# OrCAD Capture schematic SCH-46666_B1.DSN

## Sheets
1 P02_TABLES AND NOTES: title: PCF85063AT-ARD; rev: B1; company: NXP Semiconductors; note: SCH-46666 PDF: SPF-46666; note: 6501 William Cannon Drive West; note: Austin, TX 78735-8598
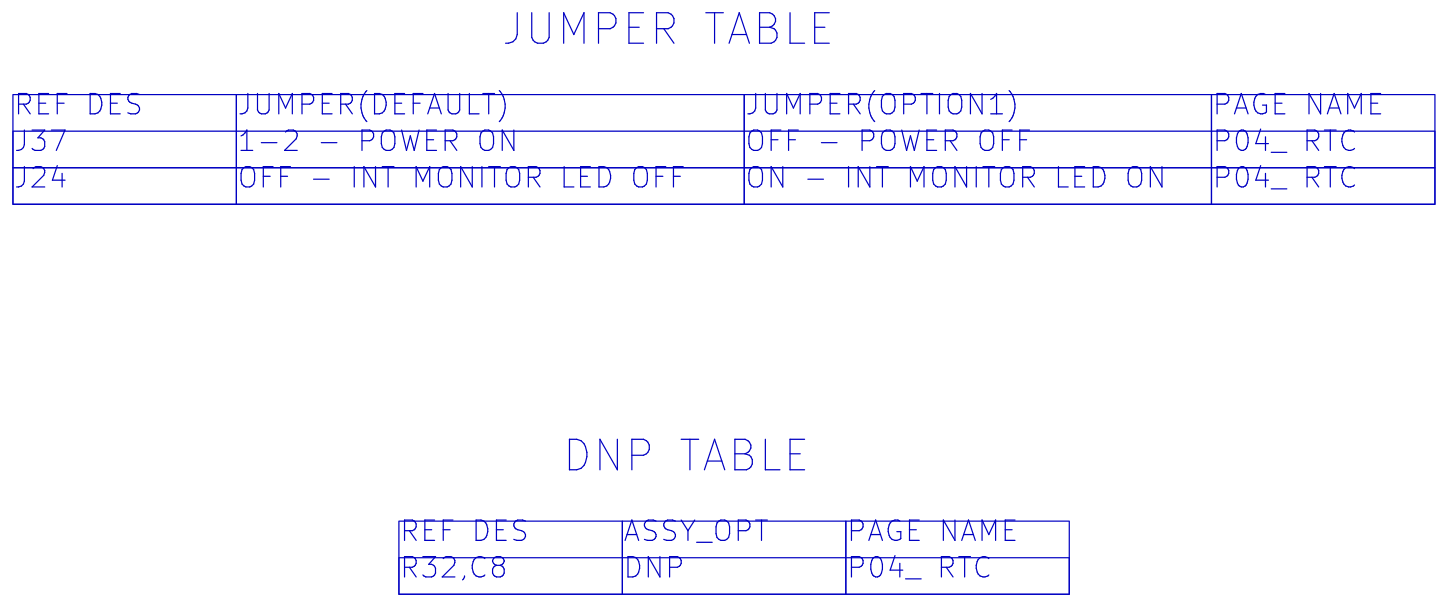
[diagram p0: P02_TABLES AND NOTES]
2 P01_COVER_PAGE
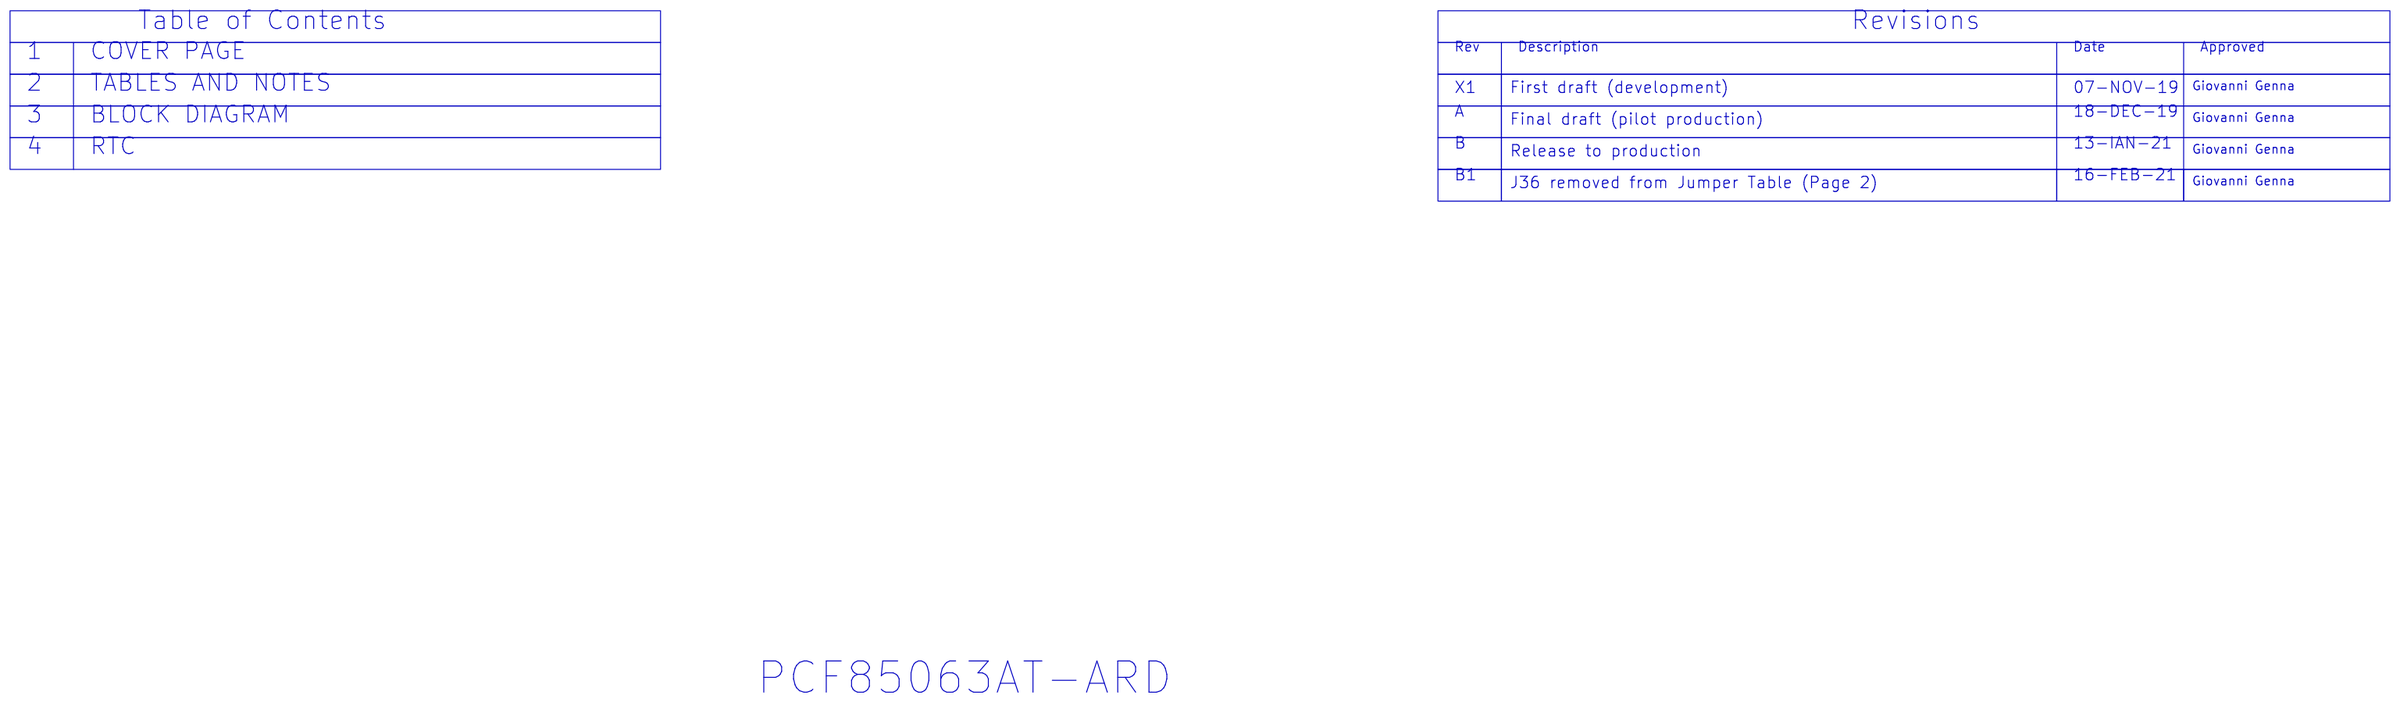
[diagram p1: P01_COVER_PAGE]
3 P03_BLOCK_DIAGRAM
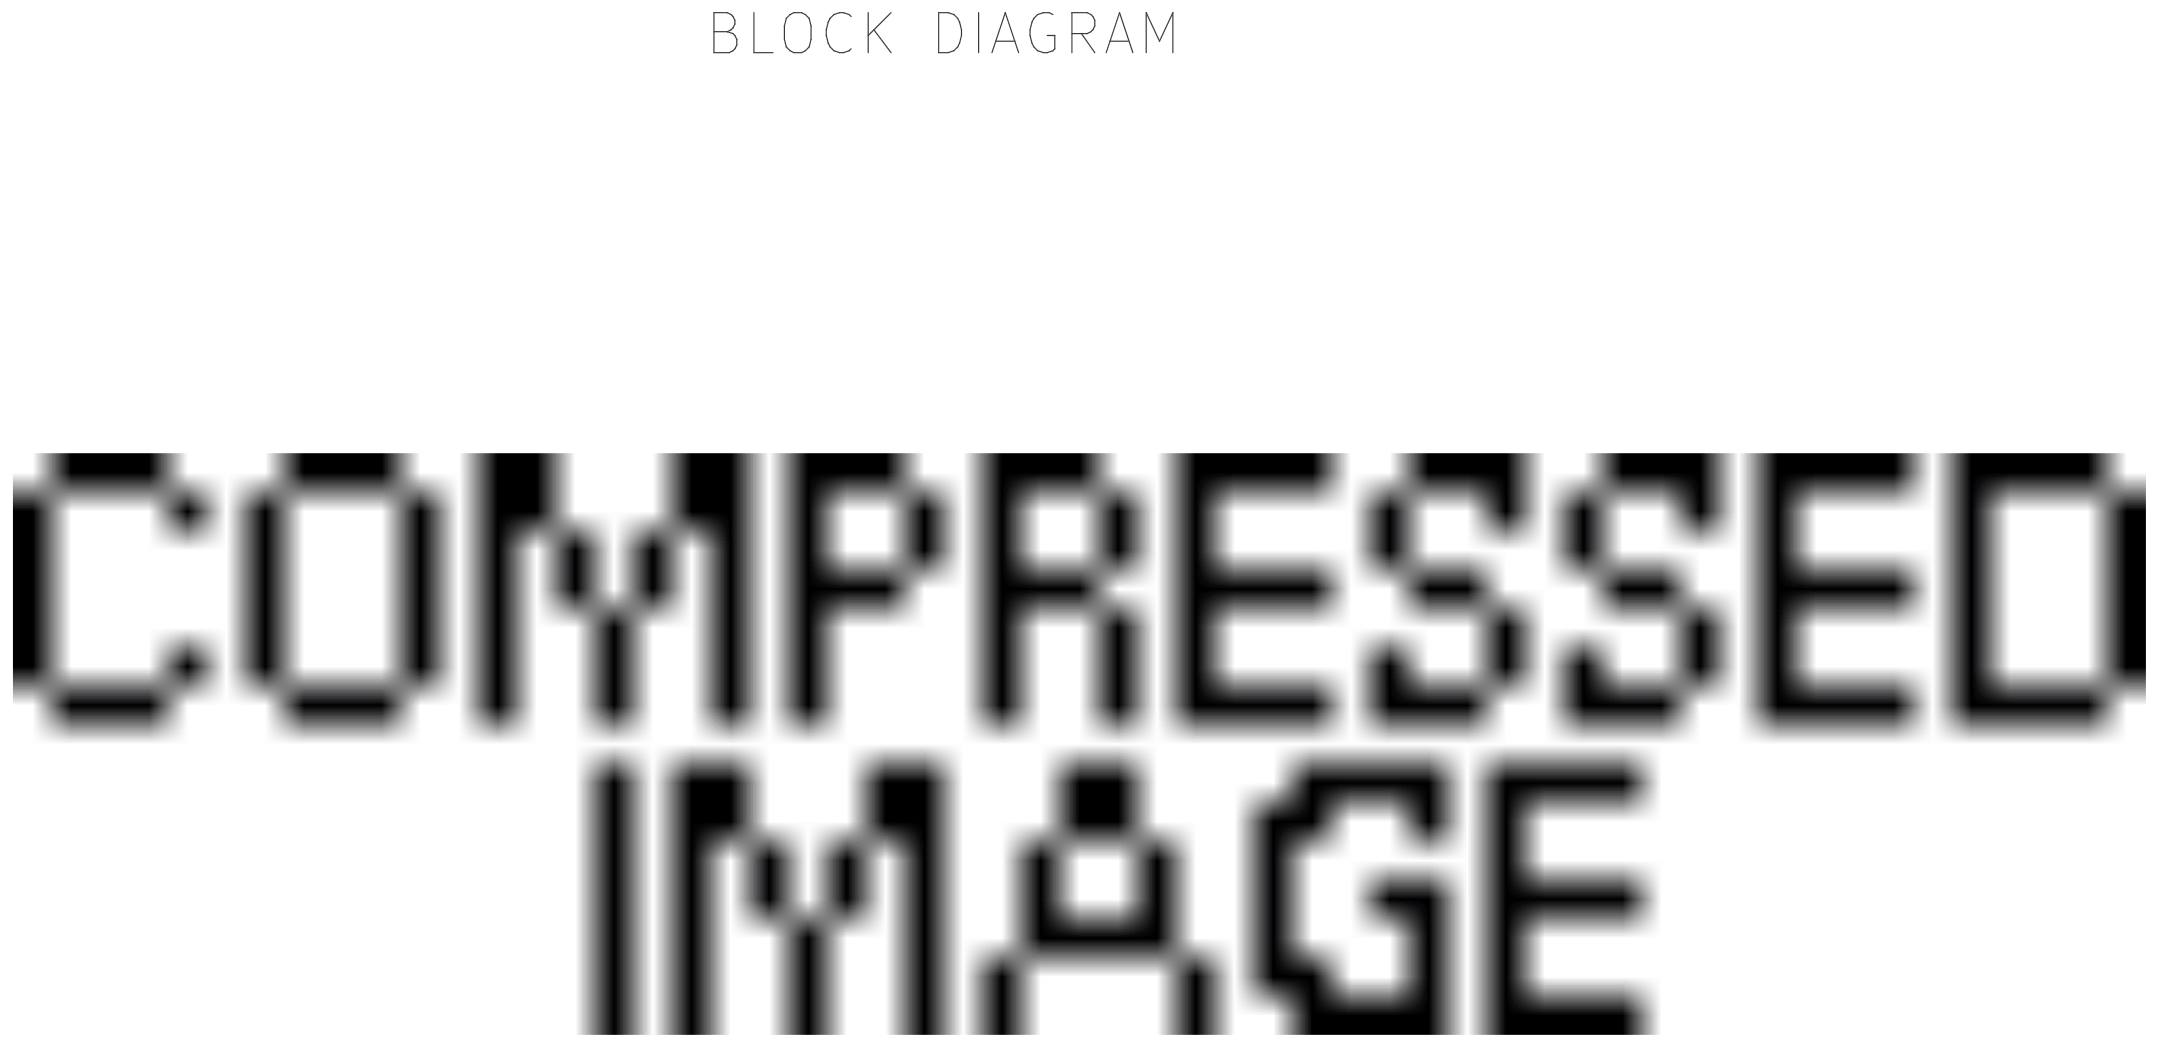
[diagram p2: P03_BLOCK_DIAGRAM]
4 P04_ RTC: size C
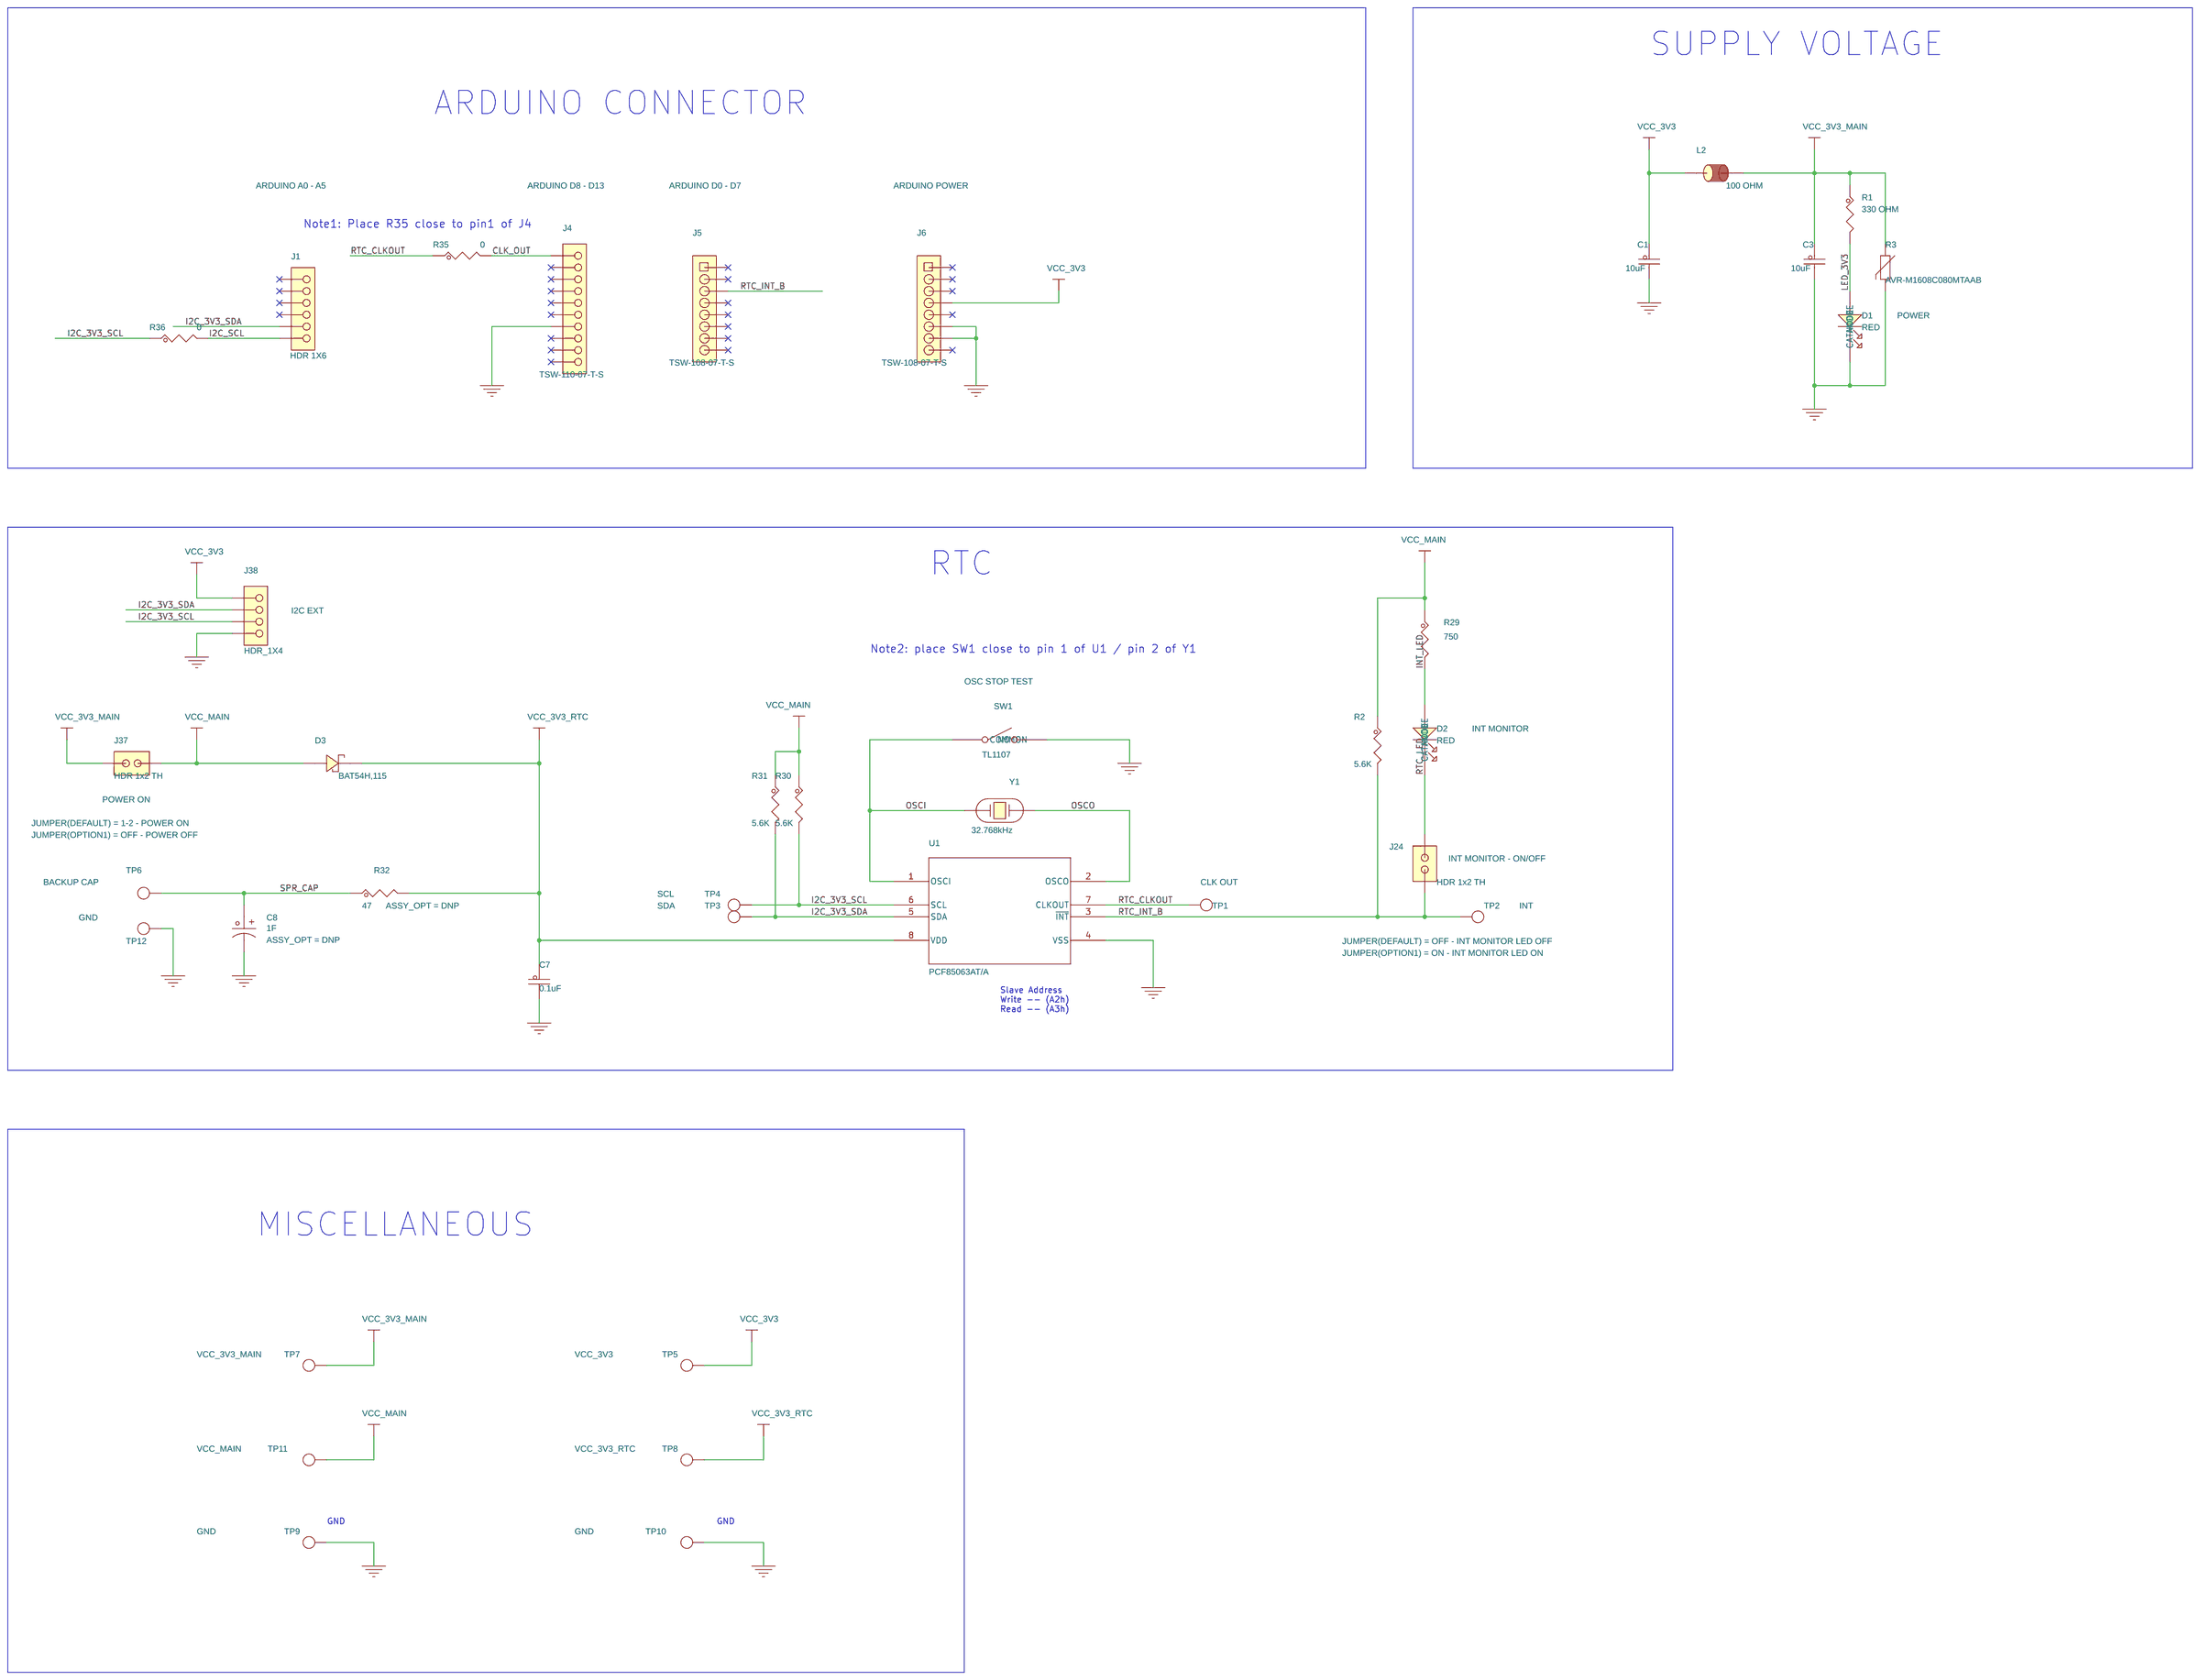
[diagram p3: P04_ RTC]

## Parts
C1  10uF  [CC0603_OV]
C3  10uF  [CC0603_OV]
C7  0.1uF  [CC0402_25]
C8  1F  [cap_5x19p2_th]
D1  RED  [led_2p_0805]
D2  RED  [led_2p_0805]
D3  BAT54H,115  [sod123w]
J1  HDR 1X6  [hdr106_th_tsw]
J4  TSW-110-07-T-S  [hdr110]
J5  TSW-108-07-T-S  [JUMP1X8-6040]
J6  TSW-108-07-T-S  [JUMP1X8-6040]
J24  HDR 1x2 TH  [hdr102_78mil_th]
J37  HDR 1x2 TH  [hdr102_78mil_th]
J38  HDR_1X4  [hdr104_2p54_th]
L2  100 OHM  [IND_1206A]
R1  330 OHM  [RC0402_25]
R2  5.6K  [RC0402_25]
R3  AVR-M1608C080MTAAB  [RC0603_OV]
R29  750  [RC0402_25]
R30  5.6K  [RC0402_25]
R31  5.6K  [RC0402_25]
R32  47  [RC0402_25]
R35  0  [RC0402_25]
R36  0  [RC0402_25]
SW1  TL1107  [sw2_6p5_6x3mm_th]
TP1  TPAD_028  [TPAD_028]
TP2  TPAD_028  [TPAD_028]
TP3  TPAD_028  [TPAD_028]
TP4  TPAD_028  [TPAD_028]
TP5  TPAD_028  [TPAD_028]
TP6  TPAD_028  [TPAD_028]
TP7  TPAD_028  [TPAD_028]
TP8  TPAD_028  [TPAD_028]
TP9  TPAD_028  [TPAD_028]
TP10  TPAD_028  [TPAD_028]
TP11  TPAD_028  [TPAD_028]
TP12  TPAD_028  [TPAD_028]
U1  PCF85063AT/A  [so8_1p27_4x5]
Y1  32.768kHz  [XTAL2-3p2x1p5-SM]

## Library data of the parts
C1 C3 = CAP_NP: CAP CER 10uF 25V 20% X5R 0603; AGILE_PN: 150-79272; CAD_APPROVED: Yes; FPLIST: CC0603_OV,CC0603; HEIGHT: 1MM; MFG_NAME01: MURATA; MFG_PN01: GRM188R61E106MA73D; Package Size: 0603; ROHS: Yes; Tolerance: 20%; VOLTAGE: 25V
C7 = CAP_NP: CAP CER 0.1uF 50V 10% X7R 0402; AGILE_PN: 150-79069; CAD_APPROVED: Yes; FPLIST: CC0402_25,CC0402_HD,0402_CC; HEIGHT: 0.6 MM; MFG_NAME01: MURATA; MFG_PN01: GRM155R71H104KE14D; ROHS: Yes; Tolerance: 10%; VOLTAGE: 50V
C8 = CAP_POL: CAP ACTVTD CRBN 1F 5.5V +80/-20% -- RADIAL; AGILE_PN: 150-80363; ASSY_OPT: DNP; CAD_APPROVED: Yes; HEIGHT: 19.5MM; MFG_NAME01: EATON; MFG_PN01: KR-5R5V105-R; ROHS: Yes; Temp Range: -25C to +70C; Temp_Range: -25C to +70C
D1 = LED: LED RED CLEAR SGL 30MA 0805; AGILE_PN: 370-76455; CAD_APPROVED: Yes; FPLIST: led_2p_0805,led0805; HEIGHT: 1.2MM; MFG_NAME01: LITE ON; MFG_PN01: LTST-C170EKT; ROHS: Yes; SILK: POWER; VOLTAGE: 5V
D2 = LED: LED RED CLEAR SGL 30MA 0805; AGILE_PN: 370-76455; CAD_APPROVED: Yes; FPLIST: led_2p_0805,led0805; HEIGHT: 1.2MM; MFG_NAME01: LITE ON; MFG_PN01: LTST-C170EKT; ROHS: Yes; SILK: INT MONITOR; VOLTAGE: 5V
D3 = DIODE_SCHTKY: DIODE SCH 200MA 30V AEC-Q101 SOD123F; AGILE_PN: 480-79798; CAD_APPROVED: Yes; HEIGHT: 1.2MM; MFG_NAME01: NEXPERIA; ROHS: Yes; Temp Range: -65 to + 125°C; Temp_Range: -65 to + 125°C
J1 = CONN_HDR_6X1: HDR 1X6 TH 100MIL SP 330H SN 100L; AGILE_PN: 210-80604; CAD_APPROVED: Yes; HEIGHT: 8.38MM; MFG_NAME01: SAMTEC; MFG_PN01: TSW-106-07-T-S; ROHS: Yes; SILK: ARDUINO A0 - A5
J4 = CONN_HDR_10X1: HDR 1X10 TH 100MIL SP 343H SN 100L; 3D_Mechanical_Footprint_File: ftp://fcl.am.freescale.net/ALLEGRO/step/hdr110_343h_100l.STEP; AGILE_PN: 210-80883; CAD_APPROVED: Yes; HEIGHT: 8.71MM; MFG_NAME01: SAMTEC; ROHS: Yes; SILK: ARDUINO D8 - D13
J5 = HDR-1X8: HDR 1X8 TH 100MIL SP 343H SN 100L; AGILE_PN: 210-80882; CAD_APPROVED: Yes; HEIGHT: 8.71MM; MFG_NAME01: SAMTEC; Package Size: 20.32 x 2.54 mm; ROHS: Yes; SILK: ARDUINO D0 - D7
J6 = HDR-1X8: HDR 1X8 TH 100MIL SP 343H SN 100L; AGILE_PN: 210-80882; CAD_APPROVED: Yes; HEIGHT: 8.71MM; MFG_NAME01: SAMTEC; Package Size: 20.32 x 2.54 mm; ROHS: Yes; SILK: ARDUINO POWER
J24 = HDR_1X2_TH: HDR 1X2 TH 2MM SP 197H AU 134L; 3D_Mechanical_Footprint_File: ftp://fcl.am.freescale.net/ALLEGRO/step/hdr102_78mil_th.STEP; AGILE_PN: 210-82288; CAD_APPROVED: yes; HEIGHT: 5MM; JUMPER(DEFAULT): OFF - INT MONITOR LED OFF; JUMPER(OPTION1): ON - INT MONITOR LED ON; MFG_NAME01: HARWIN; MFG_PN01: M22-2010205; ROHS: yes; SILK: INT MONITOR - ON/OFF
J37 = HDR_1X2_TH: HDR 1X2 TH 2MM SP 197H AU 134L; 3D_Mechanical_Footprint_File: ftp://fcl.am.freescale.net/ALLEGRO/step/hdr102_78mil_th.STEP; AGILE_PN: 210-82288; CAD_APPROVED: yes; HEIGHT: 5MM; JUMPER(DEFAULT): 1-2 - POWER ON; JUMPER(OPTION1): OFF - POWER OFF; MFG_NAME01: HARWIN; MFG_PN01: M22-2010205; ROHS: yes; SILK: POWER ON
J38 = CONN_HDR_4X1: HDR 1X4 TH 100MIL SP 352H AU 118L; AGILE_PN: 210-81270; CAD_APPROVED: Yes; HEIGHT: 8.93MM; MFG_NAME01: HARWIN INC; MFG_PN01: M20-9990445; ROHS: Yes; SILK: I2C EXT; Temp Range: -40°C to +105°C; Temp_Range: -40°C to +105°C
L2 = IND_BF: IND FER BEAD 100 OHM@100MHZ 3A -- 1206; AGILE_PN: 180-30038; CAD_APPROVED: Yes; FPLIST: IND_1206A,1206_CC; HEIGHT: 1.3MM; MFG_NAME01: LAIRD TECHNOLOGIES; MFG_PN01: HI1206N101R-10; ROHS: Yes; TOL: XXXX
R1 = RES: RES MF 330 OHM 1/16W 1% 0402; AGILE_PN: 470-80566; CAD_APPROVED: Yes; FPLIST: RC0402_25,RC0402_HD,0402_CC; HEIGHT: 0.4MM; MFG_NAME01: WALSIN TECHNOLOGY CORP.; MFG_PN01: WR04X3300FTL; ROHS: Yes; Temp_Range: -55C to +155C; Tolerance: 1%
R2 R30 R31 = RES: RES MF 5.6K 1/16W 5% 0402; AGILE_PN: 470-30316; CAD_APPROVED: Yes; HEIGHT: 0.45 MM; MFG_NAME01: SMEC; MFG_PN01: RC73L2Z562JTF; ROHS: Yes; Tolerance: 5%
R3 = VARISTOR: VARISTOR 8V 30A 650PF 0603; AGILE_PN: 470-82175; CAD_APPROVED: Yes; FPLIST: RC0603_OV,RC0603,0603_CC; HEIGHT: 0.9MM; MFG_NAME01: TDK; ROHS: Yes; Temp Range: -40C to +125C; Temp_Range: -40C to +125C; Tolerance: 20%; VOLTAGE: 5.5V
R29 = RES: RES MF 750 OHM 1/16W 5% 0402; AGILE_PN: 470-81902; CAD_APPROVED: Yes; HEIGHT: 0.4MM; MFG_NAME01: YAGEO; MFG_PN01: RC0402JR-07750RL; ROHS: Yes; Temp Range: -55C to +155C; Tolerance: 5%
R32 = RES: RES MF 47 OHM 1/16W 5% 0402; AGILE_PN: 470-75632; ASSY_OPT: DNP; CAD_APPROVED: Yes; HEIGHT: 0.41mm; MFG_NAME01: YAGEO AMERICA; MFG_PN01: RC0402JR-0747RL; ROHS: Yes; Tolerance: 5%
R35 R36 = RES: RES MF ZERO OHM 1/10W -- 0402; AGILE_PN: 470-79965; CAD_APPROVED: Yes; FPLIST: RC0402_25,RC0402_HD,RC0402_X2,0402_CC; HEIGHT: 0.4MM; MFG_NAME01: PANASONIC; MFG_PN01: ERJ-2GE0R00X; ROHS: Yes; Temp Range: –55 °C to +155 °C; Temp_Range: –55 °C to +155 °C; VOLTAGE: 1/10W
SW1 = SW2P: SW SPST TACT NO 50MA 12V TH; AGILE_PN: 510-78226; CAD_APPROVED: Yes; HEIGHT: 4.3MM; MFG_NAME01: E SWITCH; MFG_PN01: TL1107AF130WQ; ROHS: Yes; SILK: OSC STOP TEST; Temp Range: -20°C ~ 70°C
TP1 = TESTLOOP: TEST POINT PAD 28MIL DIA SMT, NO PART TO ORDER; AGILE_PN: 211-79313; CAD_APPROVED: Yes; HEIGHT: 0.1 MM; MFG_NAME01: N/A; MFG_PN01: N/A; ROHS: Yes; SILK: CLK OUT
TP2 = TESTLOOP: TEST POINT PAD 28MIL DIA SMT, NO PART TO ORDER; AGILE_PN: 211-79313; CAD_APPROVED: Yes; HEIGHT: 0.1 MM; MFG_NAME01: N/A; MFG_PN01: N/A; ROHS: Yes; SILK: INT
TP3 = TESTLOOP: TEST POINT PAD 28MIL DIA SMT, NO PART TO ORDER; AGILE_PN: 211-79313; CAD_APPROVED: Yes; HEIGHT: 0.1 MM; MFG_NAME01: N/A; MFG_PN01: N/A; ROHS: Yes; SILK: SDA
TP4 = TESTLOOP: TEST POINT PAD 28MIL DIA SMT, NO PART TO ORDER; AGILE_PN: 211-79313; CAD_APPROVED: Yes; HEIGHT: 0.1 MM; MFG_NAME01: N/A; MFG_PN01: N/A; ROHS: Yes; SILK: SCL
TP5 = TESTLOOP: TEST POINT PAD 28MIL DIA SMT, NO PART TO ORDER; AGILE_PN: 211-79313; CAD_APPROVED: Yes; HEIGHT: 0.1 MM; MFG_NAME01: N/A; MFG_PN01: N/A; ROHS: Yes; SILK: VCC_3V3
TP6 = TESTLOOP: TEST POINT PAD 28MIL DIA SMT, NO PART TO ORDER; AGILE_PN: 211-79313; CAD_APPROVED: Yes; HEIGHT: 0.1 MM; MFG_NAME01: N/A; MFG_PN01: N/A; ROHS: Yes; SILK: BACKUP CAP
TP7 = TESTLOOP: TEST POINT PAD 28MIL DIA SMT, NO PART TO ORDER; AGILE_PN: 211-79313; CAD_APPROVED: Yes; HEIGHT: 0.1 MM; MFG_NAME01: N/A; MFG_PN01: N/A; ROHS: Yes; SILK: VCC_3V3_MAIN
TP8 = TESTLOOP: TEST POINT PAD 28MIL DIA SMT, NO PART TO ORDER; AGILE_PN: 211-79313; CAD_APPROVED: Yes; HEIGHT: 0.1 MM; MFG_NAME01: N/A; MFG_PN01: N/A; ROHS: Yes; SILK: VCC_3V3_RTC
TP9 TP10 TP12 = TESTLOOP: TEST POINT PAD 28MIL DIA SMT, NO PART TO ORDER; AGILE_PN: 211-79313; CAD_APPROVED: Yes; HEIGHT: 0.1 MM; MFG_NAME01: N/A; MFG_PN01: N/A; ROHS: Yes; SILK: GND
TP11 = TESTLOOP: TEST POINT PAD 28MIL DIA SMT, NO PART TO ORDER; AGILE_PN: 211-79313; CAD_APPROVED: Yes; HEIGHT: 0.1 MM; MFG_NAME01: N/A; MFG_PN01: N/A; ROHS: Yes; SILK: VCC_MAIN
U1 = PCF85063ATT_A: IC RTC CLOCK/CALANDAR I2C W/ALARM 0.9-5.5V SO8; 3D_Mechanical_Footprint_File: ftp://fcl.am.freescale.net/ALLEGRO/step/so8_1p27_4x5.step; AGILE_PN: 312-82669; CAD_APPROVED: Yes; HEIGHT: 1.75MM; MFG_NAME01: NXP SEMICONDUCTORS; ROHS: Yes; Temp Range: -40C to +85C; VOLTAGE: 0.9-5.5V
Y1 = XTAL: XTAL 32.768KHZ 12.5pF -- SMT; AGILE_PN: 230-77879; CAD_APPROVED: Yes; HEIGHT: 0.65MM; MFG_NAME01: MICRO CRYSTAL; MFG_PN01: CM7V-T1A, 32.768KHz, 12.5pF, 20ppm, TA, QC; ROHS: Yes

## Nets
GND: C1.2 C3.2 C7.2 C8.2 D1.C(CATHODE) J4.7 J6.6 J6.7 J38.4 R3.2 SW1.2(NO) TP9.1(Pin1) TP10.1(Pin1) TP12.1(Pin1) U1.4(VSS)
VCC_3V3: C1.1 J6.4 J38.1 L2.1 TP5.1(Pin1)
VCC_3V3_MAIN: C3.1 J37.1 L2.2 R1.1 R3.1 TP7.1(Pin1)
VCC_3V3_RTC: C7.1 D3.C R32.2 TP8.1(Pin1) U1.8(VDD)
VCC_MAIN: D3.A J37.2 R2.1 R29.1 R30.1 R31.1 TP11.1(Pin1)
CLK_OUT: J4.1 R35.2
I2C_3V3_SCL: J38.3 R30.2 R36.1 TP4.1(Pin1) U1.6(SCL)
I2C_3V3_SDA: J1.5 J38.2 R31.2 TP3.1(Pin1) U1.5(SDA)
I2C_SCL: J1.6 R36.2
INT_LED: D2.A(ANODE) R29.2
LED_3V3: D1.A(ANODE) R1.2
OSCI: SW1.1(COMMON) U1.1(OSCI) Y1.2
OSCO: U1.2(OSCO) Y1.1
RTC_CLKOUT: R35.1 TP1.1(Pin1) U1.7(CLKOUT)
RTC_INT_B: J5.3 J24.2 R2.2 TP2.1(Pin1) U1.3(~{INT})
RTC_LED: D2.C(CATHODE) J24.1
SPR_CAP: C8.1 R32.1 TP6.1(Pin1)

Not connected (* = marked no-connect by the designer): J1 1* 2* 3* 4*; J4 2* 3* 4* 5* 6* 8* 9* 10*; J5 1* 2* 4* 5* 6* 7* 8*; J6 1* 2* 3* 5* 8*

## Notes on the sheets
sheet 1
- JUMPER TABLE
- REF DES
- JUMPER(DEFAULT)
- JUMPER(OPTION1)
- PAGE NAME
- J37
- 1-2 - POWER ON
- OFF - POWER OFF
- P04_ RTC
- J24
- OFF - INT MONITOR LED OFF
- ON - INT MONITOR LED ON
- P04_ RTC
- DNP TABLE
- REF DES
- ASSY_OPT
- PAGE NAME
- R32,C8
- DNP
- P04_ RTC
sheet 2
- Table of Contents
- Revisions
- 1
- COVER PAGE
- Rev
- Description
- Date
- Approved
- 2
- TABLES AND NOTES
- X1
- First draft (development)
- 07-NOV-19
- Giovanni Genna
- 3
- BLOCK DIAGRAM
- A
- 18-DEC-19
- Final draft (pilot production)
- Giovanni Genna
- 4
- RTC
- B
- Release to production
- 13-IAN-21
- Giovanni Genna
- B1
- J36 removed from Jumper Table (Page 2)
- 16-FEB-21
- Giovanni Genna
- PCF85063AT-ARD
sheet 3
- BLOCK DIAGRAM
sheet 4
- SUPPLY VOLTAGE
- ARDUINO CONNECTOR
- Note1: Place R35 close to pin1 of J4
- RTC
- Note2: place SW1 close to pin 1 of U1 / pin 2 of Y1
- Slave Address
  Write -- (A2h)
  Read -- (A3h)
- MISCELLANEOUS
- GND
- GND
